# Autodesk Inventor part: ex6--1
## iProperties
Created: 2006-03
Part Number: ex6--1
Document SubType Name: Modeling
Designer: Elise Moss
Author: Elise Moss
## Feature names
1. Extrusion1
2. Extrusion2
3. Extrusion3
